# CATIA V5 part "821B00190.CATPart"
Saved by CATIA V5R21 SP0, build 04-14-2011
Part number: 821B00190
Bounding box of the stored display mesh (mm): x -25.55 to 25.548, y -6.5 to 6.5, z -95.25 to 95.25
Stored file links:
  C:\Users\ALI OZGUN\Desktop\alhan\821B00190.CATPart
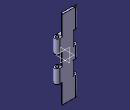
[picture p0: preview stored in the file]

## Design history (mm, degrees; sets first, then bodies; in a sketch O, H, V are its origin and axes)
Body1 (main body)
  Sketch1 on xy-plane, origin (0, 0, 0), H (1, 0, 0), V (0, 1, 0)
    construction line L1 (-19.05, 0) -> (19.05, 0)
    point P1 (-19.05, 0)
    line L2 (-19.05, 6.5) -> (19.05, 6.5)
    line L3 (19.05, -6.5) -> (-19.05, -6.5)
    arc A1 centre (19.05, 0) radius 6.5 from (19.05, 6.5) to (19.05, -6.5) cw
    arc A2 centre (-19.05, 0) radius 6.5 from (-19.05, -6.5) to (-19.05, 6.5) cw
    distance L1 L2 = 6.5
    length L1 = 38.1
    distance V P1 = 19.05
    coincidence: P1 H
    horizontal: L1 H
    tangency: A1 L2, A2 L2, A1 L3, A2 L3
  Pad1: profile Sketch1, direction (0, 0, 1), length 95.25, mirrored extent
  Sketch2 on face of Pad1 from Sketch1.L3, origin (19.05, -6.5, 0), H (-1, 0, 0), V (0, 0, 1)
    line L1 (-52.6725, 130.3302) -> (77.8049, 130.3302)
    line L2 (77.8049, 130.3302) -> (77.8049, -110.1365)
    line L3 (77.8049, -110.1365) -> (-52.6725, -110.1365)
    line L4 (-52.6725, -110.1365) -> (-52.6725, 130.3302)
    horizontal: L1 H, L3 H
    vertical: L2 V, L4 V
  Pocket1: profile Sketch2, direction (0, 1, 0), length 8
  Sketch3 on end face of Pad1, origin (0, 0, 95.25), H (1, 0, 0), V (0, 1, 0)
    arc A1 centre (19.05, 0) radius 6.5 from (12.55, 0) to (19.05, 6.5) ccw
    point P1 (19.05, 0)
    arc A2 centre (-19.05, 0) radius 6.5 from (-19.05, 6.5) to (-12.55, 0) ccw
    reference projected arc E1 centre (19.05, 0) radius 6.5 from (19.05, -6.5) to (19.05, 6.5) ccw from edge [face of Pad1 from Sketch1.A1 | end face of Pad1]
    reference projected arc E2 centre (19.05, 0) radius 6.5 from (19.05, -6.5) to (19.05, 6.5) ccw from edge [face of Pad1 from Sketch1.A1 | end face of Pad1]
    reference projected arc E3 centre (-19.05, 0) radius 6.5 from (-19.05, 6.5) to (-19.05, -6.5) ccw from edge [face of Pad1 from Sketch1.A2 | end face of Pad1]
    line L1 (-19.05, 6.5) -> (19.05, 6.5)
    line L2 (12.55, 0) -> (12.55, 1.5)
    point P3 (12.55, 0)
    line L3 (-12.55, 0) -> (-12.55, 1.5)
    point P4 (-12.55, 0)
    projected line E4 (-25.3746, 1.5) -> (25.3746, 1.5) from edge [end face of Pocket1 | end face of Pad1]
    projected line E5 (-12.55, 1.5) -> (12.55, 1.5) from edge [end face of Pocket1 | end face of Pad1]
    coincidence: P1 H, A1 E2, A2 E3, P3 A1, P3 H, P4 A2, P4 H, P3 L2, P4 L3
    concentricity: A1 E1
    tangency: L1 A1, L2 A1, L3 A2, L1 A2
  Pad2: profile Sketch3, direction (0, 0, -1), up to start face of Pad1
  Sketch4 on face of Pad1 from Sketch1.L2, origin (0, 6.5, 0), H (-1, 0, 0), V (0, 0, 1)
    line L1 (-39.6469, 109.6787) -> (-14.25, 109.6787)
    line L2 (-14.25, 109.6787) -> (-14.25, 47.8)
    line L3 (-14.25, 47.8) -> (-39.6469, 47.8)
    line L4 (-39.6469, 47.8) -> (-39.6469, 109.6787)
    point P5 (-39.6469, 15)
    line L5 (-39.6469, 15) -> (-14.25, 15)
    line L6 (-14.25, 15) -> (-14.25, -15)
    line L7 (-14.25, -15) -> (-39.6469, -15)
    line L8 (-39.6469, -15) -> (-39.6469, 15)
    point P7 (-14.25, -15)
    point P9 (-39.6469, -47.8)
    line L9 (-39.6469, -47.8) -> (-14.25, -47.8)
    line L10 (-14.25, -47.8) -> (-14.25, -127.278)
    line L11 (-14.25, -127.278) -> (-39.6469, -127.278)
    line L12 (-39.6469, -127.278) -> (-39.6469, -47.8)
    point P11 (-14.25, -127.278)
    line L13 (14.25, 48.3) -> (41.1409, 48.3)
    line L14 (41.1409, 48.3) -> (41.1409, 14.5)
    line L15 (41.1409, 14.5) -> (14.25, 14.5)
    line L16 (14.25, 14.5) -> (14.25, 48.3)
    line L17 (14.25, -14.5) -> (41.1409, -14.5)
    line L18 (41.1409, -14.5) -> (41.1409, -48.3)
    line L19 (41.1409, -48.3) -> (14.25, -48.3)
    line L20 (14.25, -48.3) -> (14.25, -14.5)
    point P19 (41.1409, -48.3)
    line L21 (27.5155, 68.3) -> (25.05, 68.3)
    point P21 (25.05, 68.3)
    line L22 (25.05, 68.3) -> (23.779, 141.1156)
    point P22 (23.779, 141.1156)
    reference projected line E1 through (19.05, 0) direction (0, 1) from axis of face of Pad1 from Sketch1.A2
    line L23 (23.779, 141.1156) -> (27.5155, 141.1156)
    point P23 (27.5155, 141.1156)
    line L24 (27.5155, 141.1156) -> (27.5155, 68.3)
    point P24 (27.5155, 68.3)
    point P25 (25.05, -68.3)
    point P26 (23.779, -141.1156)
    point P27 (27.5155, -141.1156)
    point P28 (27.5155, -68.3)
    line L25 (27.5155, -68.3) -> (25.05, -68.3)
    line L26 (25.05, -68.3) -> (23.779, -141.1156)
    line L27 (23.779, -141.1156) -> (27.5155, -141.1156)
    line L28 (27.5155, -141.1156) -> (27.5155, -68.3)
    distance L6 L20 = 28.5
    distance L16 V = 14.25
    distance L13 L15 = 33.8
    distance L17 L19 = 33.8
    distance L17 L15 = 29
    distance L17 H = 14.5
    distance L7 L9 = 32.8
    distance L5 L3 = 32.8
    distance L5 L7 = 30
    distance L7 H = 15
    distance L21 L13 = 20
    distance P21 E1 = 6
    angle L22 V = 1
    horizontal: L1 H, L3 H, L5 H, L7 H, L9 H, L11 H, L13 H, L15 H, L17 H, L19 H, L21 H, L23 H
    vertical: L2 V, L4 V, L6 V, L8 V, L10 V, L12 V, L14 V, L16 V, L18 V, L20 V, L24 V
    coincidence: P5 L4, P7 L2, P9 L4, P11 L2, P19 L14, L20 L16
    symmetry: P21 P25 H, P22 P26 H, P23 P27 H, P24 P28 H, L21 L25 H, L22 L26 H, L23 L27 H, L24 L28 H
  Pocket2: profile Sketch4, direction (0, -1, 0), length 95.25
  Sketch5 on zx-plane, origin (0, 0, 0), H (-1, 0, 0), V (0, 0, 1)
    point P1 (50.8802, 124.1518)
    line L1 (50.8802, 124.1518) -> (7.4864, 124.1518)
    line L2 (7.4864, 124.1518) -> (7.4864, 68.3)
    line L3 (7.4864, 68.3) -> (50.8802, 68.3)
    line L4 (50.8802, 68.3) -> (50.8802, 124.1518)
    point P2 (7.4864, 124.1518)
    point P3 (7.4864, 68.3)
    point P4 (50.8802, 68.3)
    reference projected line E1 (25.55, 68.3) -> (25.05, 68.3) from edge [face of Pocket2 from Sketch4.L21 | face of Pad2 from Sketch3.A2]
    point P5 (50.8802, -124.1518)
    point P6 (7.4864, -124.1518)
    point P7 (7.4864, -68.3)
    point P8 (50.8802, -68.3)
    line L5 (50.8802, -124.1518) -> (7.4864, -124.1518)
    line L6 (7.4864, -124.1518) -> (7.4864, -68.3)
    line L7 (7.4864, -68.3) -> (50.8802, -68.3)
    line L8 (50.8802, -68.3) -> (50.8802, -124.1518)
    point P9 (-40.2009, 47.8)
    line L9 (-40.2009, 47.8) -> (-4.3891, 47.8)
    line L10 (-4.3891, 47.8) -> (-4.3891, 101.6633)
    line L11 (-4.3891, 101.6633) -> (-40.2009, 101.6633)
    line L12 (-40.2009, 101.6633) -> (-40.2009, 47.8)
    point P10 (-4.3891, 47.8)
    point P11 (-4.3891, 101.6633)
    point P12 (-40.2009, 101.6633)
    point P13 (32.704, 48.3)
    line L13 (32.704, 48.3) -> (5.2293, 48.3)
    line L14 (5.2293, 48.3) -> (5.2293, 14.5)
    line L15 (5.2293, 14.5) -> (32.704, 14.5)
    line L16 (32.704, 14.5) -> (32.704, 48.3)
    point P14 (5.2293, 48.3)
    point P15 (5.2293, 14.5)
    point P16 (32.704, 14.5)
    line L17 (-8.2283, 15) -> (-32.8228, 15)
    line L18 (-32.8228, 15) -> (-32.8228, -15)
    line L19 (-32.8228, -15) -> (-8.2283, -15)
    line L20 (-8.2283, -15) -> (-8.2283, 15)
    reference projected line E2 (-25.55, -15) -> (-14.25, -15) from edge [face of Pocket2 from Sketch4.L7 | face of Pad2 from Sketch3.A1]
    reference projected line E3 (-14.25, 15) -> (-25.55, 15) from edge [face of Pocket2 from Sketch4.L5 | face of Pad2 from Sketch3.A1]
    reference projected line E4 (14.25, 14.5) -> (25.55, 14.5) from edge [face of Pocket2 from Sketch4.L15 | face of Pad2 from Sketch3.A2]
    reference projected line E5 (-25.55, 47.8) -> (-14.25, 47.8) from edge [face of Pocket2 from Sketch4.L3 | face of Pad2 from Sketch3.A1]
    reference projected line E6 (25.55, 48.3) -> (14.25, 48.3) from edge [face of Pocket2 from Sketch4.L13 | face of Pad2 from Sketch3.A2]
    point P21 (32.704, -48.3)
    point P22 (5.2293, -48.3)
    point P23 (5.2293, -14.5)
    point P24 (32.704, -14.5)
    line L21 (32.704, -48.3) -> (5.2293, -48.3)
    line L22 (5.2293, -48.3) -> (5.2293, -14.5)
    line L23 (5.2293, -14.5) -> (32.704, -14.5)
    line L24 (32.704, -14.5) -> (32.704, -48.3)
    point P25 (-40.2009, -47.8)
    point P26 (-4.3891, -47.8)
    point P27 (-4.3891, -101.6633)
    point P28 (-40.2009, -101.6633)
    line L25 (-40.2009, -47.8) -> (-4.3891, -47.8)
    line L26 (-4.3891, -47.8) -> (-4.3891, -101.6633)
    line L27 (-4.3891, -101.6633) -> (-40.2009, -101.6633)
    line L28 (-40.2009, -101.6633) -> (-40.2009, -47.8)
    horizontal: L1 H, L3 H, L9 H, L11 H, L13 H, L15 H, L17 H, L19 H
    vertical: L2 V, L4 V, L10 V, L12 V, L14 V, L16 V, L18 V, L20 V
    coincidence: L3 E1, L19 E2, L17 E3, L15 E4, L9 E5, L13 E6
    symmetry: P1 P5 H, P2 P6 H, P3 P7 H, P4 P8 H, L1 L5 H, L2 L6 H, L3 L7 H, L4 L8 H, P13 P21 H, P14 P22 H, P15 P23 H, P16 P24 H, L13 L21 H, L14 L22 H, L15 L23 H, L16 L24 H, P9 P25 H, P10 P26 H, P11 P27 H, P12 P28 H, L9 L25 H, L10 L26 H, L11 L27 H, L12 L28 H
  Pocket3: profile Sketch5, direction (0, -1, 0), length 8.2, opposite side up to end face of Pocket1
  Sketch6 on xy-plane, origin (0, 0, 0), H (1, 0, 0), V (0, 1, 0)
    circle A1 centre (-19.05, 0) radius 3.25
    point P1 (-19.05, 0)
    circle A2 centre (19.05, 0) radius 3.25
    point P2 (19.05, 0)
    reference projected arc E1 centre (19.05, 0) radius 6.5 from (12.55, 0) to (19.05, 6.5) ccw from edge [face of Pocket2 | face of Pad1]
    reference projected arc E2 centre (-19.05, 0) radius 6.5 from (-25.05, 2.5) to (-12.55, 0) ccw from edge [face of Pocket2 | face of Pad1]
    radius A2 = 3.25
    radius A1 = 3.25
    coincidence: P1 H, P2 H
    concentricity: P2 E1, P1 E2
  Pocket4: profile Sketch6, direction (0, 0, -1), length 139.2, mirrored extent
  Sketch7 on face of Pocket2, origin (0, 0, -68.3), H (1, 0, 0), V (0, -1, 0)
    circle A1 centre (-19.05, 0) radius 4.5
    reference projected arc E1 centre (-19.05, 0) radius 3.25 from (-16.2801, -1.7) to (-21.8199, -1.7) ccw from edge [face of Pocket2 | face of Pocket4 from Sketch6.A1]
    radius A1 = 4.5
    concentricity: A1 E1
  Pocket5: profile Sketch7, direction (0, 0, -1), length 139.2
  Mirror1: of Pocket5, Sketch7, about xy-plane
  Sketch8 on face of Pocket2, origin (0, 0, -14.5), H (1, 0, 0), V (0, -1, 0)
    arc A1 centre (-15.5728, -1.6782) radius 5 from (-14.25, -6.5) to (-10.576, -1.5) ccw
    point P2 (-14.25, -6.5)
    point P3 (-10.576, -1.5)
    reference projected line E1 (-12.55, -1.5) -> (-12.55, 0) from edge [face of Pad2 from Sketch3.L3 | face of Pocket2]
    reference projected line E2 (-12.55, -1.5) -> (12.55, -1.5) from edge [face of Pad2 | face of Pad1]
    reference projected line E3 (19.05, -6.5) -> (-19.05, -6.5) from edge [face of Pad2 | face of Pad1]
    reference projected line E4 (-14.25, -6.5) -> (-14.25, 88.75) from edge [face of Pocket2 from Sketch4.L20 | face of Pocket2]
    distance P3 E1 = 1.974
    radius A1 = 5
    coincidence: P3 E2, P2 E3, P2 E4
  Pocket6: profile Sketch8, direction (0, 0, -1), length 33.8
  Mirror2: of Pocket6, Sketch8, about xy-plane
  Sketch9 on face of Pocket2, origin (0, 0, 15), H (1, 0, 0), V (0, -1, 0)
    reference projected arc E1 centre (-15.5728, -1.6782) radius 5 from (-14.25, -6.5) to (-10.576, -1.5) ccw from Sketch8
    point P1 (-14.25, -6.5)
    point P2 (-10.576, -1.5)
    point P3 (14.25, -6.5)
    point P4 (10.576, -1.5)
    arc A1 centre (15.5728, -1.6782) radius 5 from (14.25, -6.5) to (10.576, -1.5) cw
    symmetry: P1 P3 V, P2 P4 V, E1 A1 V
  Pocket7: profile Sketch9, direction (0, 0, -1), length 30
  Pocket8: profile Sketch9, direction (0, 0, 1), length 88, opposite side length -32.8
  Mirror3: of Pocket8, Sketch9, about xy-plane
  Sketch10 on face of Pad2, origin (0, 1.5, 0), H (1, 0, 0), V (0, 0, 1)
    line L1 (-19.05, 49.9703) -> (19.05, 42.4604)
    line L2 (19.05, 46.1297) -> (-19.05, 53.6396)
    reference projected point E1 (-10.576, 48.3) from vertex [face of Mirror2 | face of Mirror2 | face of Pad2]
    reference projected point E2 (10.576, 47.8) from vertex [face of Pocket8 from Sketch9.A1 | start face of Pocket8 | face of Pad2]
    line L3 (19.05, 46.1297) -> (19.05, 42.4604)
    line L4 (-19.05, 53.6396) -> (-19.05, 49.9703)
    reference projected line E3 through (19.05, 0) direction (0, 1) from axis of face of Pad1
    reference projected line E4 through (-19.05, 0) direction (0, 1) from axis of face of Pad1
    point P1 (19.05, 42.4604)
    point P2 (19.05, 46.1297)
    point P3 (-19.05, 53.6396)
    point P4 (-19.05, 49.9703)
    point P5 (19.05, -42.4604)
    point P6 (19.05, -46.1297)
    point P7 (-19.05, -53.6396)
    point P8 (-19.05, -49.9703)
    line L5 (-19.05, -49.9703) -> (19.05, -42.4604)
    line L6 (19.05, -46.1297) -> (-19.05, -53.6396)
    line L7 (19.05, -46.1297) -> (19.05, -42.4604)
    line L8 (-19.05, -53.6396) -> (-19.05, -49.9703)
    distance L2 L1 = 3.6
    distance L3 E3 = 0
    distance L4 E4 = 0
    coincidence: L1 E1, L2 E2
    vertical: L3 V, L4 V
    symmetry: P1 P5 H, P2 P6 H, P3 P7 H, P4 P8 H, L1 L5 H, L2 L6 H, L3 L7 H, L4 L8 H
  Pad3: profile Sketch10, direction (0, -1, 0), length 8
  Sketch11 on face of Mirror1, origin (0, 0, 68.3), H (1, 0, 0), V (0, 1, 0)
    projected circle E1 centre (-19.05, 0) radius 3.25 from edge [face of Pocket4 from Sketch6.A1 | face of Mirror1]
    projected circle E2 centre (19.05, 0) radius 3.25 from edge [face of Pocket4 from Sketch6.A2 | start face of Pocket8]
  Pocket9: profile Sketch11, direction (0, 0, -1), length 189
  Thickness1: Face (face of Mirror1; face of Pocket5), Thickness 0.2
Body2
  Solid1: linked copy from another document
  Translate1: Direction yz-plane, ToTransfor Solid1, Length 38.1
